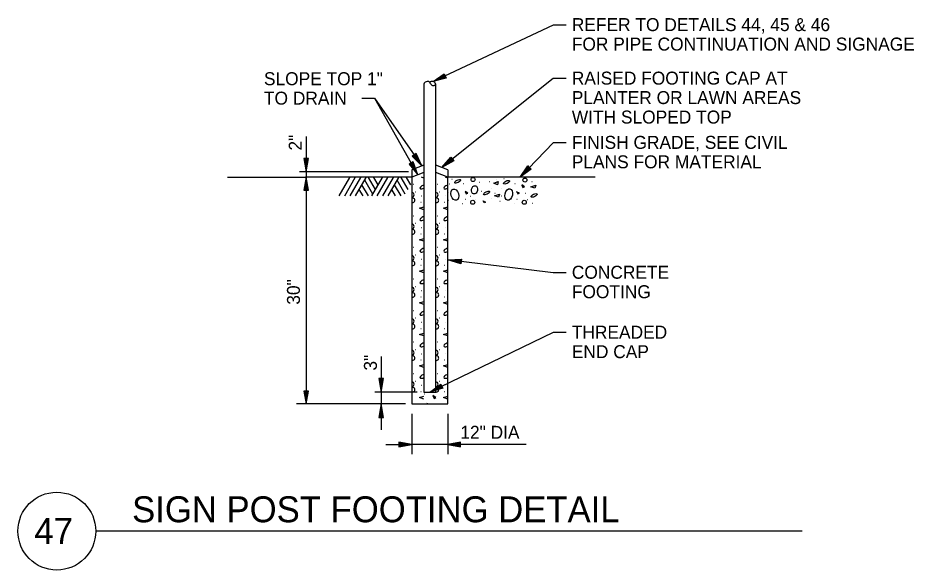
# Model space of a CAD drawing. Extents: x -121875 to -117742, y -103854 to -101122.
# Drawn here: x -120094.2 to -119679.6, y -101558.7 to -101303.3 of the extents above; entities that cross this region are included whole.
import ezdxf

# ---------------------------------------------------------------- set-up
doc = ezdxf.new("R2010")
doc.units = 0
for name, color, linetype in [('22', 7, 'Continuous'), ('C-TEXT', 7, 'Continuous'), ('S-FNDN-PILE', 7, 'Continuous')]:
    doc.layers.add(name, color=color, linetype=linetype)

# ---------------------------------------------------------------- blocks, each defined once
blk = doc.blocks.new('ARROW')
at = {"layer": 'S-FNDN-PILE'}
blk.add_lwpolyline([(-0.00208, 0.00037), (-0.00208, -0.00037), (0, 0), (-0.00208, 0.00037), (-0.00198, 0), (-0.00202, -0.00027), (-0.00045, 0.00002), (-0.00202, 0.0003), (-0.00192, 0), (-0.00192, -0.00017), (-0.00083, 0.00002), (-0.00188, 0.0002), (-0.00187, -0.00012), (-0.00122, 0), (-0.00182, 0.0001), (-0.00177, -0.00005), (-0.00155, 0), (-0.00208, 0)], dxfattribs=at)

msp = doc.modelspace()

# ---------------------------------------------------------------- linework, layer by layer
at = {"layer": '22'}
for p, q in [((-119906.41, -101333.9), (-119906.41, -101476.34)), ((-119900.87, -101476.34), (-119900.87, -101333.9)), ((-119960.88, -101358.12), (-119960.88, -101389)), ((-119900.87, -101374), (-119900.87, -101358.29)), ((-119906.41, -101371.36), (-119911.92, -101373.62)), ((-119895.35, -101373.62), (-119900.87, -101371.36)), ((-119913.41, -101374.57), (-119963.88, -101374.57)), ((-119911.92, -101373.62), (-119911.92, -101377)), ((-119906.41, -101374.74), (-119911.92, -101377)), ((-119895.35, -101377), (-119900.87, -101374.74)), ((-119895.35, -101373.62), (-119895.35, -101377)), ((-119997.22, -101377), (-119961.11, -101377)), ((-119911.92, -101377), (-119961.11, -101377)), ((-119960.88, -101377), (-119960.88, -101481.85)), ((-119945.53, -101385.67), (-119940.58, -101377.1)), ((-119943, -101385.67), (-119938.09, -101377.12)), ((-119940.48, -101385.63), (-119935.61, -101377.15)), ((-119938, -101385.63), (-119933.08, -101377.15)), ((-119930, -101384.81), (-119933.75, -101378.32)), ((-119928.74, -101382.64), (-119931.97, -101377.12)), ((-119930.5, -101385.67), (-119925.54, -101377.1)), ((-119927.5, -101380.49), (-119929.47, -101377.1)), ((-119927.95, -101385.67), (-119923.01, -101377.1)), ((-119925.42, -101385.67), (-119920.49, -101377.1)), ((-119922.91, -101385.67), (-119917.96, -101377.1)), ((-119914.97, -101384.81), (-119918.69, -101378.32)), ((-119913.7, -101382.64), (-119916.89, -101377.12)), ((-119912.46, -101380.49), (-119914.41, -101377.1)), ((-119911.92, -101377), (-119911.92, -101481.85)), ((-119895.35, -101481.85), (-119895.35, -101377)), ((-119827.14, -101377), (-119895.35, -101377)), ((-119893.45, -101377.93), (-119893.35, -101377.93)), ((-119880.65, -101379.33), (-119880.55, -101379.33)), ((-119876.15, -101379.03), (-119876.05, -101379.03)), ((-119872.8, -101377.93), (-119872.7, -101377.93)), ((-119868.5, -101377), (-119871.82, -101377)), ((-119869.3, -101377.58), (-119869.2, -101377.58)), ((-119856.4, -101379.03), (-119856.3, -101379.03)), ((-119934.53, -101385.67), (-119936.28, -101382.67)), ((-119932.02, -101385.63), (-119935.01, -101380.49)), ((-119919.47, -101385.67), (-119921.22, -101382.67)), ((-119916.95, -101385.63), (-119919.95, -101380.49)), ((-119911.29, -101380.2), (-119911.18, -101380.2)), ((-119910.17, -101383.68), (-119910.06, -101383.68)), ((-119900.25, -101380.2), (-119900.13, -101380.2)), ((-119899.13, -101383.68), (-119899.01, -101383.68)), ((-119894.45, -101380.08), (-119894.35, -101380.08)), ((-119888.15, -101379.88), (-119888.05, -101379.88)), ((-119879.8, -101383.48), (-119879.7, -101383.48)), ((-119874.95, -101382.23), (-119874.85, -101382.23)), ((-119870.65, -101382.28), (-119870.55, -101382.28)), ((-119864.25, -101379.88), (-119864.15, -101379.88)), ((-119911.92, -101386.79), (-119911.85, -101386.79)), ((-119907.46, -101385.62), (-119907.35, -101385.62)), ((-119906.49, -101385.8), (-119906.41, -101385.8)), ((-119896.42, -101385.62), (-119896.3, -101385.62)), ((-119895.1, -101387.58), (-119895, -101387.58)), ((-119894.85, -101384.03), (-119894.75, -101384.03)), ((-119887.1, -101387.08), (-119887, -101387.08)), ((-119884.8, -101385.68), (-119884.7, -101385.68)), ((-119882.4, -101387.18), (-119882.3, -101387.18)), ((-119875.3, -101386.78), (-119875.2, -101386.78)), ((-119873.55, -101384.33), (-119873.45, -101384.33)), ((-119870.4, -101385.53), (-119870.3, -101385.53)), ((-119863.35, -101387.08), (-119863.25, -101387.08)), ((-119859.35, -101384.38), (-119859.25, -101384.38)), ((-119858.4, -101387.33), (-119858.3, -101387.33)), ((-119907.82, -101388.51), (-119907.7, -101388.51)), ((-119896.77, -101388.51), (-119896.65, -101388.51)), ((-119888.45, -101389.08), (-119888.35, -101389.08)), ((-119871.15, -101388.03), (-119871.05, -101388.03)), ((-119864.65, -101389.13), (-119864.55, -101389.13)), ((-119856.1, -101388.98), (-119856, -101388.98)), ((-119911.29, -101394.8), (-119911.18, -101394.8)), ((-119900.25, -101394.8), (-119900.13, -101394.8)), ((-119910.17, -101398.28), (-119910.06, -101398.28)), ((-119907.46, -101400.22), (-119907.35, -101400.22)), ((-119906.49, -101400.39), (-119906.41, -101400.39)), ((-119899.13, -101398.28), (-119899.01, -101398.28)), ((-119896.42, -101400.22), (-119896.3, -101400.22)), ((-119911.92, -101401.39), (-119911.85, -101401.39)), ((-119907.82, -101403.1), (-119907.7, -101403.1)), ((-119896.77, -101403.1), (-119896.65, -101403.1)), ((-119911.29, -101409.4), (-119911.18, -101409.4)), ((-119900.25, -101409.4), (-119900.13, -101409.4)), ((-119911.92, -101415.99), (-119911.85, -101415.99)), ((-119910.17, -101412.88), (-119910.06, -101412.88)), ((-119907.46, -101414.82), (-119907.35, -101414.82)), ((-119906.49, -101415), (-119906.41, -101415)), ((-119899.13, -101412.88), (-119899.01, -101412.88)), ((-119896.42, -101414.82), (-119896.3, -101414.82)), ((-119907.82, -101417.71), (-119907.7, -101417.71)), ((-119896.77, -101417.71), (-119896.65, -101417.71)), ((-119911.29, -101424), (-119911.18, -101424)), ((-119900.25, -101424), (-119900.13, -101424)), ((-119910.17, -101427.47), (-119910.06, -101427.47)), ((-119907.46, -101429.42), (-119907.35, -101429.42)), ((-119899.13, -101427.47), (-119899.01, -101427.47)), ((-119896.42, -101429.42), (-119896.3, -101429.42)), ((-119911.92, -101430.59), (-119911.85, -101430.59)), ((-119907.82, -101432.3), (-119907.7, -101432.3)), ((-119906.49, -101429.59), (-119906.41, -101429.59)), ((-119896.77, -101432.3), (-119896.65, -101432.3)), ((-119911.29, -101438.6), (-119911.18, -101438.6)), ((-119900.25, -101438.6), (-119900.13, -101438.6)), ((-119911.92, -101445.19), (-119911.85, -101445.19)), ((-119910.17, -101442.07), (-119910.06, -101442.07)), ((-119907.46, -101444.01), (-119907.35, -101444.01)), ((-119906.49, -101444.19), (-119906.41, -101444.19)), ((-119899.13, -101442.07), (-119899.01, -101442.07)), ((-119896.42, -101444.01), (-119896.3, -101444.01)), ((-119907.82, -101446.9), (-119907.7, -101446.9)), ((-119896.77, -101446.9), (-119896.65, -101446.9)), ((-119911.29, -101453.19), (-119911.18, -101453.19)), ((-119900.25, -101453.19), (-119900.13, -101453.19)), ((-119910.17, -101456.67), (-119910.06, -101456.67)), ((-119899.13, -101456.67), (-119899.01, -101456.67)), ((-119926.13, -101459.88), (-119926.13, -101493.85)), ((-119911.92, -101459.79), (-119911.85, -101459.79)), ((-119907.82, -101461.5), (-119907.7, -101461.5)), ((-119907.46, -101458.62), (-119907.35, -101458.62)), ((-119906.49, -101458.79), (-119906.41, -101458.79)), ((-119896.77, -101461.5), (-119896.65, -101461.5)), ((-119896.42, -101458.62), (-119896.3, -101458.62)), ((-119911.29, -101467.79), (-119911.18, -101467.79)), ((-119900.25, -101467.79), (-119900.13, -101467.79)), ((-119911.92, -101474.39), (-119911.85, -101474.39)), ((-119910.17, -101471.27), (-119910.06, -101471.27)), ((-119907.46, -101473.21), (-119907.35, -101473.21)), ((-119906.49, -101473.39), (-119906.41, -101473.39)), ((-119899.13, -101471.27), (-119899.01, -101471.27)), ((-119896.42, -101473.21), (-119896.3, -101473.21)), ((-119909.4, -101476.34), (-119929.13, -101476.34)), ((-119907.82, -101476.1), (-119907.7, -101476.1)), ((-119906.41, -101476.34), (-119900.87, -101476.34)), ((-119906.01, -101477.1), (-119905.9, -101477.1)), ((-119896.77, -101476.1), (-119896.65, -101476.1)), ((-119914.92, -101481.85), (-119965.23, -101481.85)), ((-119911.92, -101481.85), (-119895.35, -101481.85)), ((-119911.92, -101486.35), (-119911.92, -101505.11)), ((-119895.35, -101486.35), (-119895.35, -101505.11)), ((-119923.92, -101500.61), (-119911.92, -101500.61)), ((-119895.35, -101500.61), (-119911.92, -101500.61)), ((-119859.06, -101500.61), (-119895.35, -101500.61)), ((-119731.39, -101540.67), (-120058.2, -101540.67))]:
    msp.add_line(p, q, dxfattribs=at)
for points in [[(-119840.59, -101306.62), (-119846.59, -101306.62), (-119902.12, -101332.75)], [(-119896.92, -101329.11), (-119895.99, -101331.11), (-119902.12, -101332.75), (-119896.92, -101329.11), (-119896.73, -101330.23), (-119896.3, -101330.92), (-119900.91, -101332.13), (-119897.02, -101329.38), (-119896.91, -101330.32), (-119896.7, -101330.77), (-119899.87, -101331.65), (-119897.25, -101329.82), (-119896.89, -101330.7), (-119898.81, -101331.21), (-119897.3, -101330.17), (-119897.25, -101330.64), (-119897.9, -101330.78), (-119896.45, -101330.11)], [(-119840.59, -101331.37), (-119846.59, -101331.37), (-119898.11, -101372.49)], [(-119935.14, -101340.42), (-119929.14, -101340.42), (-119912.23, -101370.42)], [(-119929.14, -101340.42), (-119929.14, -101340.42), (-119907.31, -101371.73)], [(-119840.59, -101361.08), (-119846.59, -101361.08), (-119861.79, -101377)], [(-119909.96, -101365.96), (-119911.77, -101367.21), (-119907.31, -101371.73), (-119909.96, -101365.96), (-119910.7, -101366.83), (-119911.41, -101367.21), (-119908.04, -101370.59), (-119910.01, -101366.24), (-119910.58, -101367), (-119910.99, -101367.28), (-119908.69, -101369.64), (-119910.03, -101366.74), (-119910.78, -101367.32), (-119909.39, -101368.73), (-119910.16, -101367.07), (-119910.45, -101367.45), (-119909.96, -101367.9), (-119910.87, -101366.59)], [(-119911.27, -101369.88), (-119913.19, -101370.96), (-119909.16, -101375.87), (-119911.27, -101369.88), (-119912.08, -101370.69), (-119912.83, -101370.99), (-119909.78, -101374.67), (-119911.35, -101370.16), (-119911.98, -101370.86), (-119912.42, -101371.11), (-119910.35, -101373.67), (-119911.41, -101370.65), (-119912.22, -101371.16), (-119910.95, -101372.69), (-119911.58, -101370.97), (-119911.89, -101371.33), (-119911.44, -101371.82), (-119912.23, -101370.42)], [(-119893.89, -101367.74), (-119892.53, -101369.47), (-119898.11, -101372.49), (-119893.89, -101367.74), (-119893.45, -101368.79), (-119892.87, -101369.36), (-119897.08, -101371.61), (-119893.93, -101368.02), (-119893.6, -101368.91), (-119893.29, -101369.31), (-119896.18, -101370.89), (-119894.05, -101368.51), (-119893.5, -101369.28), (-119895.25, -101370.22), (-119894.02, -101368.87), (-119893.86, -101369.31), (-119894.47, -101369.6), (-119893.21, -101368.6)], [(-119858.27, -101371.72), (-119856.67, -101373.24), (-119861.79, -101377), (-119858.27, -101371.72), (-119857.68, -101372.7), (-119857.03, -101373.18), (-119860.89, -101375.99), (-119858.26, -101372), (-119857.82, -101372.84), (-119857.46, -101373.19), (-119860.1, -101375.16), (-119858.32, -101372.5), (-119857.67, -101373.19), (-119859.27, -101374.36), (-119858.24, -101372.85), (-119858.02, -101373.27), (-119858.58, -101373.64), (-119857.47, -101372.48)], [(-119906.4, -101377.39), (-119907.46, -101377)], [(-119895.35, -101377.39), (-119896.42, -101377)], [(-119874, -101379.78), (-119871.95, -101378.98), (-119872.25, -101380.48), (-119874, -101379.78)], [(-119887.2, -101383.63), (-119886.85, -101384.68), (-119886.05, -101384.38), (-119887.3, -101383.63)], [(-119863.4, -101383.73), (-119862.9, -101384.68), (-119862.15, -101384.33), (-119863.45, -101383.68)], [(-119861.05, -101380.63), (-119860.55, -101381.78), (-119859.8, -101381.38), (-119861.05, -101380.58)], [(-119856.85, -101381.38), (-119854.55, -101380.68), (-119855.1, -101382.03), (-119856.85, -101381.38)], [(-119879, -101387.88), (-119877.8, -101388.58), (-119878.55, -101388.88), (-119879, -101387.88)], [(-119873.65, -101385.53), (-119871.45, -101384.78), (-119871.85, -101386.23), (-119873.6, -101385.53)], [(-119911.92, -101391.32), (-119911.82, -101391.27), (-119911.92, -101391.21)], [(-119908.34, -101391.27), (-119906.4, -101390.68)], [(-119906.4, -101392), (-119908.34, -101391.27)], [(-119900.87, -101391.32), (-119900.78, -101391.27), (-119900.87, -101391.21)], [(-119897.3, -101391.27), (-119895.35, -101390.68)], [(-119895.35, -101392), (-119897.3, -101391.27)], [(-119911.92, -101405.92), (-119911.82, -101405.87), (-119911.92, -101405.82)], [(-119908.34, -101405.87), (-119906.4, -101405.27)], [(-119906.4, -101406.6), (-119908.34, -101405.87)], [(-119900.87, -101405.92), (-119900.78, -101405.87), (-119900.87, -101405.82)], [(-119897.3, -101405.87), (-119895.35, -101405.27)], [(-119895.35, -101406.6), (-119897.3, -101405.87)], [(-119889.01, -101414.89), (-119889.28, -101417.08), (-119895.35, -101415.24), (-119889.01, -101414.89), (-119889.44, -101415.95), (-119889.44, -101416.76), (-119894, -101415.35), (-119889.23, -101415.07), (-119889.64, -101415.93), (-119889.7, -101416.42), (-119892.86, -101415.49), (-119889.67, -101415.32), (-119889.83, -101416.26), (-119891.72, -101415.67), (-119889.9, -101415.59), (-119890.1, -101416.02), (-119890.73, -101415.79), (-119889.14, -101415.99)], [(-119840.59, -101421.15), (-119846.59, -101421.15), (-119889.14, -101415.99)], [(-119911.92, -101420.52), (-119911.82, -101420.47), (-119911.92, -101420.41)], [(-119908.34, -101420.47), (-119906.4, -101419.88)], [(-119906.4, -101421.19), (-119908.34, -101420.47)], [(-119900.87, -101420.52), (-119900.78, -101420.47), (-119900.87, -101420.41)], [(-119897.3, -101420.47), (-119895.35, -101419.88)], [(-119895.35, -101421.19), (-119897.3, -101420.47)], [(-119911.92, -101435.12), (-119911.82, -101435.06), (-119911.92, -101435.01)], [(-119908.34, -101435.06), (-119906.4, -101434.47)], [(-119906.4, -101435.79), (-119908.34, -101435.06)], [(-119900.87, -101435.12), (-119900.78, -101435.06), (-119900.87, -101435.01)], [(-119897.3, -101435.06), (-119895.35, -101434.47)], [(-119895.35, -101435.79), (-119897.3, -101435.06)], [(-119911.92, -101449.72), (-119911.82, -101449.66), (-119911.92, -101449.61)], [(-119908.34, -101449.66), (-119906.4, -101449.07)], [(-119906.4, -101450.39), (-119908.34, -101449.66)], [(-119840.59, -101448.87), (-119846.59, -101448.87), (-119903.64, -101476.34)], [(-119900.87, -101449.72), (-119900.78, -101449.66), (-119900.87, -101449.61)], [(-119897.3, -101449.66), (-119895.35, -101449.07)], [(-119895.35, -101450.39), (-119897.3, -101449.66)], [(-119911.92, -101464.31), (-119911.82, -101464.26), (-119911.92, -101464.21)], [(-119908.34, -101464.26), (-119906.4, -101463.67)], [(-119906.4, -101464.99), (-119908.34, -101464.26)], [(-119900.87, -101464.31), (-119900.78, -101464.26), (-119900.87, -101464.21)], [(-119897.3, -101464.26), (-119895.35, -101463.67)], [(-119895.35, -101464.99), (-119897.3, -101464.26)], [(-119898.48, -101472.64), (-119897.53, -101474.62), (-119903.64, -101476.34), (-119898.48, -101472.64), (-119898.27, -101473.76), (-119897.84, -101474.44), (-119902.44, -101475.71), (-119898.57, -101472.91), (-119898.46, -101473.85), (-119898.24, -101474.3), (-119901.41, -101475.21), (-119898.8, -101473.35), (-119898.44, -101474.23), (-119900.35, -101474.76), (-119898.85, -101473.71), (-119898.8, -101474.18), (-119899.45, -101474.33), (-119898, -101473.63)], [(-119908.34, -101478.87), (-119906.4, -101478.27)], [(-119906.4, -101479.59), (-119908.34, -101478.87)], [(-119902.25, -101477.98), (-119901.66, -101479.34), (-119900.78, -101478.87), (-119902.25, -101477.92)], [(-119897.3, -101478.87), (-119895.35, -101478.27)], [(-119895.35, -101479.59), (-119897.3, -101478.87)], [(-119904.51, -101481.85), (-119905.07, -101481.57)], [(-119905.02, -101481.63), (-119904.9, -101481.85)]]:
    msp.add_lwpolyline(points, dxfattribs=at)
for centre, radius in [((-119883.62, -101378.04), 0.926), ((-119859.62, -101378.29), 0.926), ((-119883.76, -101388.58), 0.926), ((-119859.91, -101388.58), 0.926), ((-120076.2, -101540.67), 18)]:
    msp.add_circle(centre, radius, dxfattribs=at)
for centre, radius, start, end in [((-119904.78, -101334.41), 1.7, 20.1247, 162.5936), ((-119902.67, -101334.61), 1.94, 21.3058, 125.2094), ((-119902.01, -101333.37), 1.26, 201.4301, 334.7726), ((-119911.96, -101385.16), 1.09, 272.0624, 87.9376), ((-119911.62, -101387.64), 1.09, 254.0755, 105.9245), ((-119900.91, -101385.15), 1.09, 272.0624, 87.9376), ((-119900.57, -101387.64), 1.09, 254.0755, 105.9245), ((-119911.96, -101399.75), 1.09, 272.0624, 87.9376), ((-119900.91, -101399.75), 1.09, 272.0624, 87.9376), ((-119911.62, -101402.24), 1.09, 254.0755, 105.9245), ((-119900.57, -101402.24), 1.09, 254.0755, 105.9245), ((-119911.96, -101414.35), 1.09, 272.0624, 87.9376), ((-119911.62, -101416.84), 1.09, 254.0755, 105.9245), ((-119900.91, -101414.35), 1.09, 272.0624, 87.9376), ((-119900.57, -101416.84), 1.09, 254.0755, 105.9245), ((-119911.96, -101428.95), 1.09, 272.0624, 87.9376), ((-119900.91, -101428.95), 1.09, 272.0624, 87.9376), ((-119911.62, -101431.44), 1.09, 254.0755, 105.9245), ((-119900.57, -101431.44), 1.09, 254.0755, 105.9245), ((-119911.96, -101443.55), 1.09, 272.0624, 87.9376), ((-119911.62, -101446.04), 1.09, 254.0755, 105.9245), ((-119900.91, -101443.55), 1.09, 272.0624, 87.9376), ((-119900.57, -101446.04), 1.09, 254.0755, 105.9245), ((-119911.96, -101458.15), 1.09, 272.0624, 87.9376), ((-119900.91, -101458.15), 1.09, 272.0624, 87.9376), ((-119911.62, -101460.64), 1.09, 254.0755, 105.9245), ((-119900.57, -101460.64), 1.09, 254.0755, 105.9245), ((-119911.96, -101472.75), 1.09, 272.0624, 87.9376), ((-119911.62, -101475.24), 1.09, 254.0755, 105.9245), ((-119900.91, -101472.75), 1.09, 272.0624, 87.9376), ((-119900.57, -101475.24), 1.09, 254.0755, 105.9245)]:
    msp.add_arc(centre, radius, start, end, dxfattribs=at)
for centre, major_axis, ratio in [((-119890.75, -101378.89), (-1.37, -0.64), 0.393469), ((-119868.15, -101379.29), (-1.37, -0.64), 0.393469), ((-119892.06, -101385.05), (-0.82, 2.58), 0.634119), ((-119882.95, -101382.83), (-0.39, -1.9), 0.736889), ((-119877.34, -101384.3), (-1.37, -0.64), 0.393469), ((-119867.11, -101384.96), (0.58, 2.65), 0.634119), ((-119855.34, -101385.4), (-1.37, -0.64), 0.393469)]:
    msp.add_ellipse(centre, major_axis=major_axis, ratio=ratio, dxfattribs=at)
for centre in [(-119906.58, -101381.41), (-119895.53, -101381.41), (-119906.58, -101396.01), (-119895.53, -101396.01), (-119906.58, -101410.61), (-119895.53, -101410.61), (-119906.58, -101425.21), (-119895.53, -101425.21), (-119906.58, -101439.81), (-119895.53, -101439.8), (-119906.58, -101454.4), (-119895.53, -101454.4), (-119906.58, -101469), (-119895.53, -101469)]:
    msp.add_ellipse(centre, major_axis=(-1.61, -0.76), ratio=0.393469, start_param=4.419925, end_param=7.780473, dxfattribs=at)
at = {"layer": 'C-TEXT'}
msp.add_lwpolyline([(-119909.16, -101372.48), (-119909.16, -101372.49), (-119909.16, -101372.48)], close=True, dxfattribs=at)

# ---------------------------------------------------------------- block references
at = {"layer": '22'}
for p, xscale, yscale, rotation in [((-119960.88, -101374.57), 2995.2755905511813, 2995.705082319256, -90), ((-119960.88, -101377), 2880, 2945.454545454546, 90), ((-119926.13, -101476.34), 2995.2755905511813, 2995.705082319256, -90), ((-119960.88, -101481.85), 2880, 2945.454545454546, -90), ((-119926.13, -101481.85), 2995.2755905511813, 2995.705082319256, 90), ((-119895.35, -101500.61), 2880, 2945.454545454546, 180)]:
    msp.add_blockref('ARROW', p, dxfattribs=dict(at, xscale=xscale, yscale=yscale, rotation=rotation))
at = {"layer": '22', "xscale": 2880, "yscale": 2945.454545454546}
msp.add_blockref('ARROW', (-119911.92, -101500.61), dxfattribs=at)

# ---------------------------------------------------------------- texts
at = {"layer": '22'}
for s, height, p in [('REFER TO DETAILS 44, 45 & 46', 6, (-119837.92, -101309.41)), ('FOR PIPE CONTINUATION AND SIGNAGE', 6, (-119837.92, -101318.41)), ('SLOPE TOP 1"', 6, (-119980.37, -101334.42)), ('RAISED FOOTING CAP AT', 6, (-119837.92, -101334.16)), ('TO DRAIN', 6, (-119980.37, -101343.42)), ('PLANTER OR LAWN AREAS', 6, (-119837.92, -101343.16)), ('WITH SLOPED TOP', 6, (-119837.92, -101352.16)), ('FINISH GRADE, SEE CIVIL', 6, (-119837.92, -101363.87)), ('PLANS FOR MATERIAL', 6, (-119837.92, -101372.87)), ('CONCRETE', 6, (-119837.92, -101423.94)), ('FOOTING', 6, (-119837.92, -101432.94)), ('THREADED', 6, (-119837.92, -101451.66)), ('END CAP', 6, (-119837.92, -101460.66)), ('12" DIA', 6, (-119889.5, -101497.96)), ('SIGN POST FOOTING DETAIL', 12, (-120041.37, -101536.57)), ('47', 12, (-120086.59, -101546.57))]:
    msp.add_text(s, height=height, dxfattribs=at).set_placement(p)
for s, p in [('2"', (-119962.87, -101364.66)), ('30"', (-119963.72, -101435.95)), ('3"', (-119928.12, -101466.42))]:
    msp.add_text(s, height=6, rotation=90, dxfattribs=at).set_placement(p)

doc.saveas('drawing.dxf')
